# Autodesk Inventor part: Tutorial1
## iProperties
Shininess: 77.0
Length Units: 11269
Angle Units: 11279
Time Units: 11290
Mass Units: 11283
Length Display Precision: 3
Angle Display Precision: 2
Created: 2001-12
Part Number: Tutorial1
Document SubType Name: Modeling
Designer: Renu Muthoo
Density: 0.0
Volumn: 0.0
Area: 0.0
PropertySet Name: Model Information
Control State: 0
Master: False
Checked Out: False
Author: Renu Muthoo
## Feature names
1. Extrusion1
2. Extrusion2
3. Extrusion3
4. Fillet1
5. Hole2
6. Hole3
